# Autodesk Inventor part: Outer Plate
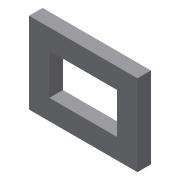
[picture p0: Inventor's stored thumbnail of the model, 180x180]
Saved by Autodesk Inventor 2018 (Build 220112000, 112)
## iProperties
Created: 2017-06
Part Number: Outer Plate
Material: Generic
Document SubType Name: Modeling
Designer: CADCIM 00
Density: 1 g/cm^3
Appearance: Default
Author: CADCIM 00
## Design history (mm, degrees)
sketch "Sketch1"
  geometry: L1 (0, 0)-(80, 0); L2 (80, 0)-(80, 60); L3 (80, 60)-(0, 60); L4 (0, 60)-(0, 0); L5 (10, 50)-(70, 50); L6 (70, 50)-(70, 10); L7 (70, 10)-(10, 10); L8 (10, 10)-(10, 50)
  constraints: 16 end point, 4 parallel, 2 horizontal, 2 perpendicular
  dimensions: "d0" = 80 distance of L2.end L3.end; "d1" = 60 distance of L1.end L2.end; "d2" = 10 distance between parallel lines of L3 L5; "d3" = 40 distance of L7.end L5.start; "d4" = 60 distance of L5.start L5.end; "d5" = 10 distance between parallel lines of L4 L8
extrude "Extrusion1" new body sketch "Sketch1" distance "d6" = 10; taper "d7" = 0 deg
body "Solid1"
